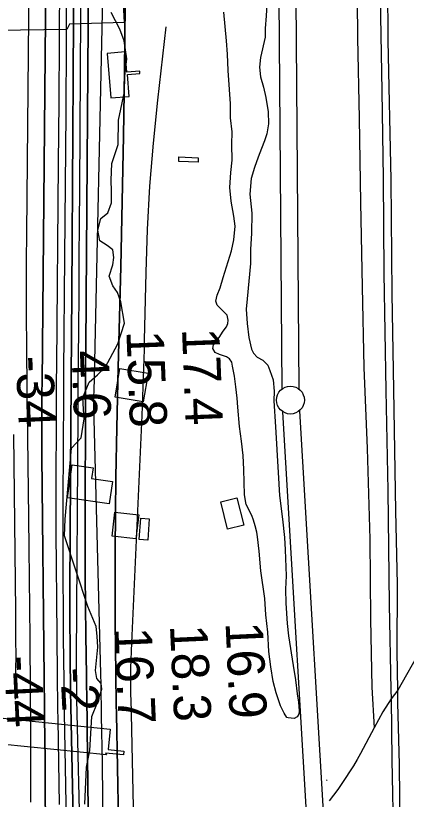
# Model space of a CAD drawing. Extents: x 3651524 to 3689615, y 505651 to 531377.
# Drawn here: x 3660133 to 3660835, y 520255 to 521661 of the extents above; entities that cross this region are included whole.
import ezdxf

# ---------------------------------------------------------------- set-up
doc = ezdxf.new("R2010")
doc.units = 0
for name, color, linetype in [('V-BLDG-OTLN', 7, 'Continuous'), ('V-CHAN-DOCK', 7, 'Continuous'), ('V-RAIL-TRAK', 7, 'Continuous'), ('V-RIVR-EDGE', 7, 'Continuous'), ('V-RIVR-RANG', 7, 'Continuous'), ('V-ROAD-CNTR', 7, 'Continuous'), ('V-RRAP-RVMT', 7, 'Continuous'), ('V-SITE-VEGE', 7, 'Continuous'), ('V-SURV-LINE', 7, 'Continuous'), ('V-TOPO-DPTH', 7, 'Continuous'), ('V-TOPO-MAJR', 7, 'Continuous'), ('V-TOPO-MINR', 7, 'Continuous'), ('V-TOPO-WATR', 7, 'Continuous')]:
    doc.layers.add(name, color=color, linetype=linetype)

msp = doc.modelspace()

# ---------------------------------------------------------------- linework, layer by layer
at = {"layer": 'V-BLDG-OTLN'}
for points in [[(3660460.978, 521398.412), (3660426.162, 521399.619), (3660426.432, 521407.407), (3660461.248, 521406.203)], [(3660371.019, 521019.153), (3660362.438, 520967.935), (3660311.615, 520976.451), (3660320.204, 521027.667)], [(3660530.626, 520795.499), (3660542.756, 520746.868), (3660513.838, 520739.655), (3660501.708, 520788.286)], [(3660349.235, 520721.946), (3660306.485, 520726.81), (3660311.375, 520769.828), (3660354.129, 520764.964)], [(3660372.903, 520758.136), (3660370.454, 520719.799), (3660355.225, 520720.772), (3660357.674, 520759.109)]]:
    msp.add_lwpolyline(points, close=True, dxfattribs=at)
at = {"layer": 'V-CHAN-DOCK'}
for points in [[(3660355.954, 521561.74), (3660332.762, 521559.774), (3660329.699, 521595.921), (3660297.33, 521593.177), (3660304.086, 521513.469), (3660337.25, 521516.281), (3660333.942, 521555.285), (3660355.917, 521557.147), (3660355.954, 521561.74)], [(3660301.256, 520784.86), (3660226.037, 520795.692), (3660234.579, 520855.018), (3660272.203, 520849.602), (3660269.428, 520830.334), (3660307.267, 520824.884), (3660301.256, 520784.86)], [(3660296.281, 520334.345), (3660011.779, 520363.126), (3660016.488, 520409.675), (3660303.148, 520380.677), (3660299.454, 520344.135), (3660327.655, 520341.282), (3660326.958, 520334.415), (3660294.782, 520337.669), (3660296.281, 520334.345)]]:
    msp.add_lwpolyline(points, dxfattribs=at)
at = {"layer": 'V-RAIL-TRAK'}
for points in [[(3660824.231, 520140.654), (3660822.628, 520317.228), (3660819.857, 520427.691), (3660819.531, 520450.635), (3660818.544, 520520.416), (3660818.9, 520640.863), (3660815.902, 520771.997), (3660812.668, 520989.93), (3660809.211, 521161.815), (3660807.507, 521366.142), (3660802.488, 521616.582), (3660801.238, 521813.224)], [(3660787.33, 521727.856), (3660790.837, 521525.267), (3660793.395, 521369.343), (3660794.513, 521198.681), (3660797.882, 520988.421), (3660801.793, 520808.854), (3660804.087, 520604.517), (3660807.278, 520450.942), (3660807.446, 520435.086), (3660808.607, 520325.744), (3660811.82, 520173.35)]]:
    msp.add_lwpolyline(points, dxfattribs=at)
at = {"layer": 'V-RIVR-EDGE'}
msp.add_lwpolyline([(3660257.297, 520246.133), (3660260.524, 520312.3), (3660266.113, 520342.309), (3660269.939, 520402.96), (3660280.419, 520428.669), (3660287.831, 520452.547), (3660286.63, 520462.353), (3660278.687, 520471.564), (3660276.271, 520485.662), (3660280.665, 520527.93), (3660279.488, 520547.54), (3660277.692, 520564.701), (3660262.463, 520600.889), (3660221.11, 520727.213), (3660221.797, 520757.235), (3660233.141, 520884.654), (3660250.957, 520903.605), (3660255.942, 520937.293), (3660254.761, 520955.065), (3660253.587, 520975.9), (3660265.297, 521003.444), (3660280.034, 521016.275), (3660294.16, 521029.72), (3660316.935, 521071.942), (3660328.669, 521109.289), (3660322.023, 521147.295), (3660315.939, 521164.466), (3660307.389, 521176.129), (3660301.304, 521193.3), (3660307.483, 521214.118), (3660309.353, 521226.98), (3660307.55, 521241.078), (3660297.764, 521248.455), (3660284.306, 521257.066), (3660280.676, 521276.069), (3660286.242, 521296.888), (3660298.523, 521307.274), (3660305.307, 521325.027), (3660305.358, 521345.859), (3660304.795, 521366.081), (3660306.093, 521395.488), (3660317.207, 521429.774), (3660317.928, 521473.275), (3660328.47, 521524.106), (3660329.152, 521552.29), (3660332.906, 521583.529), (3660328.084, 521616.016), (3660320.17, 521636.868), (3660304.926, 521666.929)], dxfattribs=at)
at = {"layer": 'V-ROAD-CNTR'}
for points in [[(3660746.123, 521756.476), (3660746.985, 521621.503), (3660749.991, 521476.748), (3660752.883, 521325.506), (3660755.777, 521174.263), (3660758.321, 521029.516), (3660764.565, 520884.243), (3660769.57, 520721.368), (3660770.748, 520578.039), (3660773.23, 520456.021), (3660777.277, 520382.768)], [(3660860.799, 520523.775), (3660819.531, 520450.635), (3660807.446, 520435.086), (3660792.655, 520411.696), (3660777.277, 520382.768), (3660752.838, 520336.803), (3660746.391, 520325.813), (3660739.774, 520314.928), (3660732.989, 520304.149), (3660726.036, 520293.483), (3660718.919, 520282.93), (3660711.643, 520272.498), (3660704.206, 520262.184), (3660696.612, 520251.997)], [(3660691.301, 520289.466), (3660693.007, 520288.59)]]:
    msp.add_lwpolyline(points, dxfattribs=at)
at = {"layer": 'V-RRAP-RVMT'}
for p, q in [((3660315.844, 521859.78), (3660328.168, 521648.881)), ((3660229.803, 521645.905), (3660225.004, 521636.155)), ((3660328.168, 521648.881), (3660229.803, 521645.905)), ((3660225.004, 521636.155), (3660006.987, 521632.69))]:
    msp.add_line(p, q, dxfattribs=at)
at = {"layer": 'V-SITE-VEGE'}
for points in [[(3660584.382, 521681.468), (3660582.938, 521661.003)], [(3660582.938, 521661.003), (3660581.451, 521637.84), (3660581.175, 521622.203), (3660572.991, 521586.216), (3660571.058, 521568.454), (3660572.909, 521551.162), (3660578.514, 521532.728), (3660582.504, 521514.323), (3660586.899, 521488.358), (3660587.595, 521466.774), (3660584.587, 521449.033), (3660580.054, 521436.708), (3660574.955, 521422.777), (3660568.747, 521407.247), (3660561.944, 521388.494), (3660556.201, 521368.64), (3660553.549, 521340.644), (3660557.262, 521306.602), (3660556.623, 521270.482), (3660555.03, 521241.386), (3660555.122, 521216.038), (3660549.154, 521153.05), (3660547.204, 521134.208), (3660548.902, 521108.293), (3660551.7, 521083.436), (3660556.719, 521062.313), (3660560.369, 521055.239), (3660567.254, 521048.108), (3660577.404, 521042.535), (3660585.877, 521033.756), (3660590.018, 521023.976), (3660595.662, 521007.697), (3660597.456, 520987.174), (3660596.612, 520969.932), (3660600.094, 520922.951), (3660604.579, 520840.9), (3660607.088, 520799.87), (3660612.267, 520757.173), (3660616.007, 520724.749), (3660617.236, 520702.621), (3660619.102, 520655.666), (3660618.143, 520631.954), (3660618.235, 520606.606), (3660620.83, 520570.428), (3660623.136, 520548.277), (3660631.897, 520494.732), (3660635.76, 520469.317), (3660639.088, 520443.911), (3660640.978, 520428.778), (3660642.33, 520413.654), (3660641.675, 520407.195), (3660638.904, 520402.929), (3660633.456, 520399.789), (3660622.692, 520401.059), (3660620.545, 520401.636), (3660615.286, 520409.279), (3660609.046, 520422.331), (3660601.37, 520445.654), (3660595.804, 520466.249), (3660591.406, 520492.211), (3660588.117, 520519.773), (3660586.043, 520554.864), (3660582.811, 520585.661), (3660580.63, 520614.821), (3660573.419, 520664.563), (3660570.814, 520700.202), (3660567.488, 520725.607), (3660566.562, 520734.252), (3660563.527, 520745.631), (3660560.463, 520755.394), (3660557.381, 520764.075), (3660547.481, 520783.664), (3660544.012, 520800.984), (3660543.334, 520823.645), (3660543.205, 520846.839), (3660542.025, 520871.667), (3660538.709, 520897.611), (3660535.392, 520923.555), (3660532.238, 520958.664), (3660530.896, 520974.327), (3660528.564, 520994.862), (3660526.21, 521014.318), (3660522.751, 521032.175), (3660521.258, 521039.211), (3660517.05, 521045.218), (3660511.715, 521048.548), (3660499.394, 521053.081), (3660491.362, 521056.46), (3660487.174, 521063.544), (3660488.376, 521070.534), (3660498.847, 521083.291), (3660506.064, 521095.03), (3660512.128, 521102.47), (3660514.389, 521108.362), (3660515.045, 521114.824), (3660513.04, 521123.487), (3660504.557, 521131.726), (3660495.023, 521141.601), (3660492.992, 521148.648), (3660495.339, 521159.392), (3660500.428, 521172.784)], [(3660500.428, 521172.784), (3660506.144, 521191.022), (3660521.009, 521238.754), (3660525.135, 521258.634), (3660527.191, 521283.407), (3660525.348, 521301.235), (3660520.433, 521328.287), (3660517.627, 521352.605), (3660519.72, 521379.532), (3660522.268, 521401.597), (3660521.686, 521429.65), (3660522.084, 521452.293), (3660519.298, 521477.688), (3660519.208, 521503.038), (3660517.498, 521528.413), (3660514.865, 521562.437), (3660513.771, 521592.116), (3660512.034, 521615.875), (3660509.255, 521641.811), (3660507.008, 521667.198)]]:
    msp.add_lwpolyline(points, dxfattribs=at)
at = {"layer": 'V-SURV-LINE'}
for points in [[(3660611.636, 520990.937), (3660600.277, 522471.798)], [(3660630.276, 522472.033), (3660641.635, 520991.173)], [(3660642.938, 520952.004), (3660694.869, 520069.957)], [(3660664.92, 520068.212), (3660612.989, 520950.261)]]:
    msp.add_lwpolyline(points, dxfattribs=at)
msp.add_circle((3660626.789, 520971.083), 25, dxfattribs=at)
at = {"layer": 'V-TOPO-DPTH'}
for points in [[(3660266.37, 522052.65), (3660259.75, 521154.194), (3660259.526, 521123.989), (3660259.302, 521093.784), (3660259.076, 521063.579), (3660258.85, 521033.374), (3660258.484, 520984.76), (3660258.444, 520978.862), (3660258.411, 520972.965), (3660258.388, 520967.067), (3660258.371, 520961.169), (3660257.981, 520763.868), (3660258, 520710), (3660258.186, 520656.133), (3660258.622, 520602.268), (3660259.224, 520548.403), (3660260.181, 520477.633), (3660260.437, 520459.155), (3660260.703, 520440.676), (3660260.982, 520422.198), (3660261.27, 520403.72), (3660261.557, 520385.242), (3660261.834, 520366.764), (3660262.096, 520348.286), (3660262.347, 520329.808), (3660263.57, 520236.938)], [(3660263.57, 520236.938), (3660262.347, 520329.808), (3660262.096, 520348.286), (3660261.834, 520366.764), (3660261.557, 520385.242), (3660261.27, 520403.72), (3660260.982, 520422.198), (3660260.703, 520440.676), (3660260.437, 520459.155), (3660260.181, 520477.633), (3660259.224, 520548.403), (3660258.622, 520602.268), (3660258.186, 520656.133), (3660258, 520710), (3660257.981, 520763.868), (3660258.371, 520961.169), (3660258.388, 520967.067), (3660258.411, 520972.965), (3660258.444, 520978.862), (3660258.484, 520984.76), (3660258.85, 521033.374), (3660259.076, 521063.579), (3660259.302, 521093.784), (3660259.526, 521123.989), (3660259.75, 521154.194), (3660266.37, 522052.65)], [(3660160.371, 520249.358), (3660160.503, 520289.567), (3660160.525, 520337.061), (3660160.509, 520353.524), (3660160.463, 520369.986), (3660160.37, 520386.449), (3660160.247, 520402.911), (3660160.047, 520425.301), (3660160, 520430.568), (3660159.951, 520435.836), (3660159.902, 520441.103), (3660159.852, 520446.371), (3660158.911, 520543.746), (3660158.37, 520597.7), (3660157.8, 520651.655), (3660157.188, 520705.609), (3660156.549, 520759.562), (3660154.186, 520952.732), (3660154.089, 520960.869), (3660153.997, 520969.006), (3660153.912, 520977.144), (3660153.832, 520985.281), (3660153.029, 521069.632), (3660152.693, 521119.945), (3660152.546, 521170.258), (3660152.684, 521220.571), (3660153.012, 521270.884), (3660160.238, 522044.457)], [(3660160.371, 520249.358), (3660160.503, 520289.567), (3660160.525, 520337.061), (3660160.509, 520353.524), (3660160.463, 520369.986), (3660160.37, 520386.449), (3660160.247, 520402.911), (3660160.047, 520425.301), (3660160, 520430.568), (3660159.951, 520435.836), (3660159.902, 520441.103), (3660159.852, 520446.371), (3660158.911, 520543.746), (3660158.37, 520597.7), (3660157.8, 520651.655), (3660157.188, 520705.609), (3660156.549, 520759.562), (3660154.186, 520952.732), (3660154.089, 520960.869), (3660153.997, 520969.006), (3660153.912, 520977.144), (3660153.832, 520985.281), (3660153.029, 521069.632), (3660152.693, 521119.945), (3660152.546, 521170.258), (3660152.684, 521220.571), (3660153.012, 521270.884), (3660160.238, 522044.457)], [(3660239.026, 521990.952), (3660236.656, 521547.642), (3660236.103, 521451.68), (3660235.495, 521355.718), (3660234.808, 521259.757), (3660234.066, 521163.797), (3660232.81, 521009.586), (3660232.664, 520990.731), (3660232.53, 520971.876), (3660232.411, 520953.021), (3660232.304, 520934.166), (3660230.703, 520630.839), (3660230.613, 520598.913), (3660230.628, 520566.987), (3660230.8, 520535.062), (3660231.077, 520503.137), (3660231.592, 520456.839), (3660231.703, 520448.063), (3660231.831, 520439.288), (3660231.984, 520430.513), (3660232.155, 520421.739), (3660240.594, 520018.818)], [(3660240.594, 520018.818), (3660232.155, 520421.739), (3660231.984, 520430.513), (3660231.831, 520439.288), (3660231.703, 520448.063), (3660231.592, 520456.839), (3660231.077, 520503.137), (3660230.8, 520535.062), (3660230.628, 520566.987), (3660230.613, 520598.913), (3660230.703, 520630.839), (3660232.304, 520934.166), (3660232.411, 520953.021), (3660232.53, 520971.876), (3660232.664, 520990.731), (3660232.81, 521009.586), (3660234.066, 521163.797), (3660234.808, 521259.757), (3660235.495, 521355.718), (3660236.103, 521451.68), (3660236.656, 521547.642), (3660239.026, 521990.952)], [(3660187.726, 521785.909), (3660180.444, 521002.622), (3660180.31, 520986.149), (3660180.202, 520969.675), (3660180.134, 520953.201), (3660180.091, 520936.727), (3660180.096, 520920.253), (3660180.139, 520903.779), (3660180.24, 520887.305), (3660180.379, 520870.831), (3660184.427, 520472.425), (3660184.606, 520454.727), (3660184.785, 520437.029), (3660184.961, 520419.331), (3660185.137, 520401.633), (3660185.889, 520325.719), (3660186.354, 520270.063), (3660186.704, 520214.407)], [(3660187.726, 521785.909), (3660180.444, 521002.622), (3660180.31, 520986.149), (3660180.202, 520969.675), (3660180.134, 520953.201), (3660180.091, 520936.727), (3660180.096, 520920.253), (3660180.139, 520903.779), (3660180.24, 520887.305), (3660180.379, 520870.831), (3660184.427, 520472.425), (3660184.606, 520454.727), (3660184.785, 520437.029), (3660184.961, 520419.331), (3660185.137, 520401.633), (3660185.889, 520325.719), (3660186.354, 520270.063), (3660186.704, 520214.407)], [(3660211.625, 520245.233), (3660209.312, 520397.509), (3660209.017, 520417.844), (3660208.741, 520438.178), (3660208.493, 520458.513), (3660208.264, 520478.849), (3660206.834, 520613.964), (3660206.33, 520673.431), (3660205.992, 520732.9), (3660205.905, 520792.369), (3660205.983, 520851.838), (3660206.172, 520906.933), (3660206.307, 520938.856), (3660206.476, 520970.778), (3660206.696, 521002.7), (3660206.95, 521034.622), (3660210.118, 521396.014), (3660211.009, 521506.302), (3660211.802, 521616.591), (3660212.444, 521726.88)], [(3660211.625, 520245.233), (3660209.312, 520397.509), (3660209.017, 520417.844), (3660208.741, 520438.178), (3660208.493, 520458.513), (3660208.264, 520478.849), (3660206.834, 520613.964), (3660206.33, 520673.431), (3660205.992, 520732.9), (3660205.905, 520792.369), (3660205.983, 520851.838), (3660206.172, 520906.933), (3660206.307, 520938.856), (3660206.476, 520970.778), (3660206.696, 521002.7), (3660206.95, 521034.622), (3660210.118, 521396.014), (3660211.009, 521506.302), (3660211.802, 521616.591), (3660212.444, 521726.88)], [(3660329.688, 521679.827), (3660328.437, 521562.401), (3660326.78, 521444.982), (3660324.513, 521327.573), (3660321.84, 521210.171), (3660317.26, 521029.612), (3660316.597, 521002.494), (3660315.966, 520975.375), (3660315.385, 520948.255), (3660314.835, 520921.134), (3660313.128, 520832.881), (3660312.168, 520767.941), (3660311.601, 520702.999), (3660311.626, 520638.054), (3660312.045, 520573.108), (3660313.081, 520478.978), (3660313.298, 520461.096), (3660313.543, 520443.214), (3660313.829, 520425.333), (3660314.142, 520407.453), (3660317.712, 520216.101)]]:
    msp.add_lwpolyline(points, dxfattribs=at)
at = {"layer": 'V-TOPO-MAJR'}
msp.add_lwpolyline([(3660133.09, 520434.562), (3660133.418, 520460.85), (3660133.635, 520487.139), (3660133.706, 520513.429), (3660133.693, 520539.719), (3660133.556, 520566.009), (3660133.335, 520592.299), (3660129.911, 520909.583)], dxfattribs=at)
at = {"layer": 'V-TOPO-MINR'}
for points in [[(3660160.371, 520249.358), (3660160.503, 520289.567), (3660160.525, 520337.061), (3660160.509, 520353.524), (3660160.463, 520369.986), (3660160.37, 520386.449), (3660160.247, 520402.911), (3660160.047, 520425.301), (3660160, 520430.568), (3660159.951, 520435.836), (3660159.902, 520441.103), (3660159.852, 520446.371), (3660158.911, 520543.746), (3660158.37, 520597.7), (3660157.8, 520651.655), (3660157.188, 520705.609), (3660156.549, 520759.562), (3660154.186, 520952.732), (3660154.089, 520960.869), (3660153.997, 520969.006), (3660153.912, 520977.144), (3660153.832, 520985.281), (3660153.029, 521069.632), (3660152.693, 521119.945), (3660152.546, 521170.258), (3660152.684, 521220.571), (3660153.012, 521270.884), (3660160.238, 522044.457)], [(3660240.594, 520018.818), (3660232.155, 520421.739), (3660231.984, 520430.513), (3660231.831, 520439.288), (3660231.703, 520448.063), (3660231.592, 520456.839), (3660231.077, 520503.137), (3660230.8, 520535.062), (3660230.628, 520566.987), (3660230.613, 520598.913), (3660230.703, 520630.839), (3660232.304, 520934.166), (3660232.411, 520953.021), (3660232.53, 520971.876), (3660232.664, 520990.731), (3660232.81, 521009.586), (3660234.066, 521163.797), (3660234.808, 521259.757), (3660235.495, 521355.718), (3660236.103, 521451.68), (3660236.656, 521547.642), (3660239.026, 521990.952)], [(3660256.243, 519885.637), (3660243.176, 520433.528), (3660243.107, 520436.678), (3660243.045, 520439.828), (3660242.996, 520442.978), (3660242.954, 520446.129), (3660242.763, 520462.8), (3660242.662, 520474.286), (3660242.601, 520485.773), (3660242.601, 520497.259), (3660242.641, 520508.746), (3660245.333, 520947.705), (3660245.412, 520960.063), (3660245.495, 520972.422), (3660245.584, 520984.78), (3660245.677, 520997.139), (3660246.47, 521098.646), (3660246.948, 521161.759), (3660247.406, 521224.871), (3660247.834, 521287.984), (3660248.241, 521351.097), (3660252.141, 521977.884)], [(3660186.704, 520214.407), (3660186.354, 520270.063), (3660185.889, 520325.719), (3660185.137, 520401.633), (3660184.961, 520419.331), (3660184.785, 520437.029), (3660184.606, 520454.727), (3660184.427, 520472.425), (3660180.379, 520870.831), (3660180.24, 520887.305), (3660180.139, 520903.779), (3660180.096, 520920.253), (3660180.091, 520936.727), (3660180.134, 520953.201), (3660180.202, 520969.675), (3660180.31, 520986.149), (3660180.444, 521002.622), (3660187.726, 521785.909)], [(3660225.576, 520149.009), (3660220.869, 520409.734), (3660220.623, 520424.236), (3660220.398, 520438.738), (3660220.204, 520453.241), (3660220.031, 520467.744), (3660219.203, 520544.038), (3660218.752, 520596.688), (3660218.462, 520649.339), (3660218.412, 520701.991), (3660218.521, 520754.643), (3660219.247, 520920.573), (3660219.373, 520945.95), (3660219.521, 520971.328), (3660219.699, 520996.705), (3660219.898, 521022.083), (3660221.649, 521228.806), (3660222.665, 521357.545), (3660223.583, 521486.285), (3660224.355, 521615.026), (3660225.028, 521743.768)], [(3660211.625, 520245.233), (3660209.312, 520397.509), (3660209.017, 520417.844), (3660208.741, 520438.178), (3660208.493, 520458.513), (3660208.264, 520478.849), (3660206.834, 520613.964), (3660206.33, 520673.431), (3660205.992, 520732.9), (3660205.905, 520792.369), (3660205.983, 520851.838), (3660206.172, 520906.933), (3660206.307, 520938.856), (3660206.476, 520970.778), (3660206.696, 521002.7), (3660206.95, 521034.622), (3660210.118, 521396.014), (3660211.009, 521506.302), (3660211.802, 521616.591), (3660212.444, 521726.88)], [(3660290.438, 520196.747), (3660289.792, 520258.047), (3660288.953, 520319.345), (3660287.592, 520404.235), (3660287.261, 520423.087), (3660286.893, 520441.938), (3660286.468, 520460.788), (3660286.006, 520479.638), (3660274.11, 520937.131), (3660273.97, 520943.209), (3660273.853, 520949.288), (3660273.771, 520955.366), (3660273.712, 520961.446), (3660273.697, 520967.525), (3660273.717, 520973.604), (3660273.79, 520979.683), (3660273.898, 520985.761), (3660290.111, 521721.085)], [(3660317.712, 520216.101), (3660314.142, 520407.453), (3660313.829, 520425.333), (3660313.543, 520443.214), (3660313.298, 520461.096), (3660313.081, 520478.978), (3660312.045, 520573.108), (3660311.626, 520638.054), (3660311.601, 520702.999), (3660312.168, 520767.941), (3660313.128, 520832.881), (3660314.835, 520921.134), (3660315.385, 520948.255), (3660315.966, 520975.375), (3660316.597, 521002.494), (3660317.26, 521029.612), (3660321.84, 521210.171), (3660324.513, 521327.573), (3660326.78, 521444.982), (3660328.437, 521562.401), (3660329.688, 521679.827)], [(3660351.089, 519933.825), (3660340.334, 520435.426), (3660340.253, 520439.961), (3660340.191, 520444.495), (3660340.16, 520449.03), (3660340.149, 520453.565), (3660340.171, 520474.801), (3660340.289, 520489.952), (3660340.542, 520505.1), (3660340.998, 520520.243), (3660341.59, 520535.383), (3660360.284, 520943.489), (3660361.023, 520960.398), (3660361.716, 520977.308), (3660362.339, 520994.222), (3660362.915, 521011.137), (3660363.431, 521028.054), (3660363.913, 521044.972), (3660364.344, 521061.892), (3660364.741, 521078.812), (3660367.405, 521200.022), (3660370.172, 521277.477), (3660374.352, 521354.835), (3660380.653, 521432.05), (3660388.369, 521509.168), (3660403.412, 521641.213)]]:
    msp.add_lwpolyline(points, dxfattribs=at)
at = {"layer": 'V-TOPO-WATR'}
msp.add_lwpolyline([(3660263.57, 520236.938), (3660262.347, 520329.808), (3660262.096, 520348.286), (3660261.834, 520366.764), (3660261.557, 520385.242), (3660261.27, 520403.72), (3660260.982, 520422.198), (3660260.703, 520440.676), (3660260.437, 520459.155), (3660260.181, 520477.633), (3660259.224, 520548.403), (3660258.622, 520602.268), (3660258.186, 520656.133), (3660258, 520710), (3660257.981, 520763.868), (3660258.371, 520961.169), (3660258.388, 520967.067), (3660258.411, 520972.965), (3660258.444, 520978.862), (3660258.484, 520984.76), (3660258.85, 521033.374), (3660259.076, 521063.579), (3660259.302, 521093.784), (3660259.526, 521123.989), (3660259.75, 521154.194), (3660266.37, 522052.65)], dxfattribs=at)

# ---------------------------------------------------------------- texts
at = {"layer": 'V-RIVR-RANG'}
for s, rotation, p in [('17.4', 272.258326, (3660431.849, 521099.139)), ('15.8', 272.258326, (3660331.937, 521094.943)), ('4.6', 272.258326, (3660233.262, 521059.381)), ('-34', 272.546444, (3660133.164, 521049.465)), ('18.3', 272.608326, (3660410.218, 520566.783)), ('16.9', 272.608326, (3660510.091, 520571.847)), ('16.7', 272.608326, (3660310.334, 520561.983)), ('-44', 272.892972, (3660112.033, 520511.618)), ('-2', 272.892972, (3660213.236, 520490.338))]:
    msp.add_text(s, height=67, rotation=rotation, dxfattribs=at).set_placement(p)

doc.saveas('drawing.dxf')
